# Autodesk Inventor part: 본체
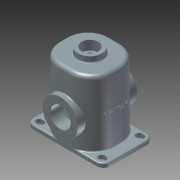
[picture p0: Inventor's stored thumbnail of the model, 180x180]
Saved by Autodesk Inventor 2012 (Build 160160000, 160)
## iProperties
Company: 한국ATC센터
Created: 2014-10
Part Number: 본체
Document SubType Name: Modeling
Designer: 한국ATC센터
Density: 2.71 g/cm^3
Material: 알루미늄-6061
Mass: 2951.76 g
Surface Area: 2149.68 cm^2
Volume: 1089.21 cm^3
Author: KYOUNG IL JANG
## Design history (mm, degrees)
sketch "스케치1"
  geometry: L1 (-70, 65)-(70, 65); L2 (70, 65)-(70, -65); L3 (70, -65)-(-70, -65); L4 (-70, -65)-(-70, 65); 3 further points
  constraints: 8 end point, 2 midpoint, 2 parallel, 1 horizontal, 1 horizontal alignment, 1 perpendicular, 1 vertical alignment
  dimensions: "d0" = 140 distance of L2.end L3.end; "d68" = 130 distance of L3.end L1.start
extrude "돌출1" new body sketch "스케치1" distance "d1" = 180; taper "d2" = 0 deg
fillet "모깎기1" dims "d3" = 55
feature "쉘1" dims "d4" = 10
sketch "스케치2"
  geometry: L1 (-70, 10)-(-70, -10) reference; L2 (-15, -65)-(-82, -65); L3 (-82, 65)-(-15, 65); L4 (-83, 57)-(-78, 57); L5 (-78, 41)-(-83, 41); L6 (-100, 47)-(-100, -47); A1 r 55 centre (-15, 10) between (-15, 65) and (-70, 10) reference; A2 r 55 centre (-15, -10) between (-70, -10) and (-15, -65) reference; A3 r 8 centre (-78, 49) between (-78, 41) and (-78, 57); A4 r 8 centre (-83, 49) between (-83, 57) and (-83, 41); A5 r 18 centre (-82, 47) between (-82, 65) and (-100, 47); A6 r 18 centre (-82, -47) between (-100, -47) and (-82, -65); 1 further point
  constraints: 10 end point, 9 tangent, 8 point on circle, 4 centre point, 2 parallel, 2 perpendicular, 1 equal radius
  dimensions: "d6" = 49 vertical distance of point (0, 0) A3.centre; "d8" = 16 distance between parallel lines of L4 L5; "d64" = 18 radius of A5; "d65" = 8 distance from line of A3.centre L1; "d66" = 30 distance between parallel lines of L6 L1; "d67" = 5 distance of A4.centre A3.centre
extrude "돌출2" join sketch "스케치2" distance "d9" = 10; taper "d10" = 0 deg
extrude "돌출3" cut sketch "스케치2" stored distance "d11" = 10; taper "d12" = 0 deg
sketch "스케치3"
  geometry: L1 (-65, 10)-(-65, 180) reference; L2 (-55, 0)-(-55, 170) reference; L3 (-77, 75)-(-45, 75); L4 (10, 0)-(-10, 0) reference; L5 (-77, 75)-(-77, 120.5); L6 (-77, 120.5)-(-55, 120.5); L7 (-55, 120.5)-(-45, 110.5); L8 (-45, 110.5)-(-45, 75); 3 further points
  constraints: 10 end point, 4 perpendicular, 1 point on line
  dimensions: "d13" = 75 distance between parallel lines of L3 L4; "d14" = 12 distance from line of L1 L3.start; "d15" = 10 distance from line of L3.end L2; "d16" = 91 diameter of L6 L3; "d17" = 135 deg angle of L7 L2
revolve "회전1" sketch "스케치3" stored, may be unused: angle "d18" = 90 deg
sketch "스케치4"
  geometry: C1 r 45.5 at (0, 0) reference; 2 further points
  constraints: 1 vertical alignment
  dimensions: "d19" = 35 distance of C1.centre point (0, 35)
hole "구멍1" sketch "스케치4" at (0, 35) diameter "d20" = 3.459; stored, may be unused: countersink angle "d24" = 90 deg, drill point angle "d26" = 118 deg; dims "d21" = 13, "d22" = 4, "d23" = 2, "d25" = 16
fillet "모깎기2" dims "d30" = 3
hole "구멍2" diameter "d33" = 52; stored, may be unused: countersink angle "d37" = 90 deg, drill point angle "d39" = 118 deg; dims "d31" = 10, "d32" = 10, "d34" = 13, "d35" = 4, "d36" = 2, "d38" = 16
sketch "스케치5"
  geometry: C1 r 31 at (0, 0); 1 further point
  constraints: 1 centre point, 1 coincident
  dimensions: "d40" = 62 diameter of C1
extrude "돌출4" join sketch "스케치5" distance "d41" = 15; taper "d42" = 0 deg
hole "구멍3" diameter "d45" = 43; stored, may be unused: countersink angle "d49" = 90 deg, drill point angle "d51" = 118 deg; dims "d43" = 10, "d44" = 10, "d46" = 13, "d47" = 4, "d48" = 2, "d50" = 16
fillet "모깎기3" dims "d52" = 3
fillet "모깎기4" dims "d53" = 3
chamfer "모따기1" distance "d55" = 1; stored, may be unused: second distance "d56" = 2, angle "d57" = 45 deg
sketch "스케치6"
  geometry: 2 further points
  constraints: 1 vertical alignment, 1 other
  dimensions: "d71" = 90 distance of point (0, 0) point (0, 90)
feature "엠보싱2" sketch "스케치6" dims "d0" = 140, "d68" = 130, "d72" = 1, "d73" = 0
fillet "모깎기6" dims "d74" = 10
sketch "스케치7"
  geometry: C1 r 15 at (0, 0); C2 r 21.5 at (0, 0) reference; C3 r 25 at (0, 0); 1 further point
  constraints: 2 centre point, 2 coincident
  dimensions: "d61" = 30 diameter of C1; "d75" = 50 diameter of C3
extrude "돌출5" join sketch "스케치7" distance "d62" = 10; taper "d63" = 0 deg
feature "면 이동1" dims "d76" = 1
node "솔리드1"
mirror "대칭1"
mirror "대칭2"
pattern_circular "원형 패턴1" dims angle "d28" = 360 deg
mirror "대칭3"
